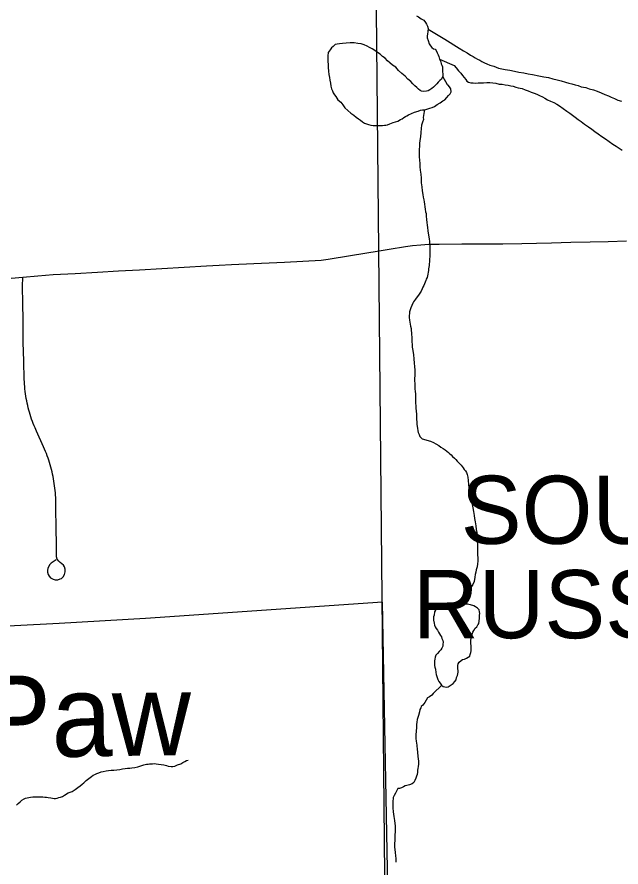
# Model space of a CAD drawing. Extents: x 103424 to 290657, y 38711 to 110967.
# Drawn here: x 117188 to 121647, y 46874 to 53149 of the extents above; entities that cross this region are included whole.
import ezdxf

# ---------------------------------------------------------------- set-up
doc = ezdxf.new("R2010")
doc.units = 0
for name, color, linetype in [('GM_X_Corporation', 7, 'Continuous'), ('GM_X_Corporation_Text', 7, 'Continuous'), ('GM_X_Minor_Lake', 7, 'Continuous'), ('GM_X_Minor_Lake_Text', 7, 'Continuous'), ('GM_X_Minor_River', 7, 'Continuous'), ('GM_X_Township_Road', 7, 'Continuous')]:
    doc.layers.add(name, color=color, linetype=linetype)

msp = doc.modelspace()

# ---------------------------------------------------------------- linework, layer by layer
at = {"layer": 'GM_X_Corporation'}
for points in [[(103423.7, 70904.9), (103423.7, 43132.7), (108691.3, 43264.4), (116952, 43470.9), (119934.2, 43543), (119908.2, 46302.1), (119859.8, 51426.6), (119800.4, 57496.9), (119747.3, 63220.6), (119711.4, 67089.1)], [(149451.3, 44180.8), (147524, 44122.7), (147511.7, 44122.4), (144100.1, 44042.4), (133604.6, 43873.3), (130307.3, 43800.5), (126993.8, 43728), (121865.1, 43580.2), (119934.2, 43543), (119908.2, 46302.1), (119859.8, 51426.6), (119800.4, 57496.9), (119747.3, 63220.6), (119711.4, 67089.1)], [(116953.7, 43492.4), (117668.8, 43508.8), (118194.1, 43520.8), (118895.2, 43536.8), (119961.9, 43561.2), (119932.5, 46334.5), (119886.4, 48829.9), (118136.2, 48708), (117498.8, 48671.3), (116838, 48636.4)]]:
    msp.add_lwpolyline(points, dxfattribs=at)
at = {"layer": 'GM_X_Minor_Lake'}
for points in [[(120331.6, 52709.7), (120327.7, 52701.6), (120321.8, 52691.4), (120309.9, 52681.1), (120298, 52668.8), (120286.1, 52656.5), (120276.2, 52646.2), (120262.3, 52631.8), (120250.3, 52621.5), (120236.4, 52611.2), (120224.4, 52604.9), (120210.3, 52600.7), (120190.2, 52598.3), (120174, 52602.1), (120163.9, 52606), (120151.6, 52615.9), (120139.3, 52627.8), (120124.9, 52641.7), (120110.6, 52655.6), (120094.1, 52673.5), (120073.6, 52691.3), (120053.1, 52711.2), (120028.5, 52733), (120003.9, 52754.8), (119983.4, 52778.8), (119958.9, 52794.5), (119940.5, 52810.4), (119924, 52826.3), (119905.6, 52844.1), (119887.2, 52858), (119868.8, 52873.8), (119850.4, 52887.7), (119830, 52901.5), (119809.6, 52913.3), (119791.2, 52925.1), (119772.9, 52934.9), (119750.5, 52944.6), (119728.2, 52950.3), (119704, 52954), (119677.7, 52957.6), (119647.4, 52959.1), (119617.1, 52956.6), (119591, 52954.1), (119568.8, 52951.8), (119550.7, 52947.4), (119536.6, 52945.2), (119522.7, 52930.8), (119510.8, 52920.5), (119501, 52906.2), (119485.1, 52887.7), (119483.6, 52861.5), (119481.9, 52841.2), (119482.2, 52821), (119484.6, 52798.9), (119485, 52776.6), (119487.5, 52748.4), (119489.9, 52724.2), (119494.3, 52702), (119496.7, 52681.9), (119501.1, 52659.7), (119505.4, 52639.6), (119509.8, 52619.5), (119516.1, 52603.4), (119522.4, 52589.4), (119530.7, 52575.4), (119541.1, 52561.4), (119555.6, 52537.4), (119578.1, 52519.6), (119592.5, 52501.7), (119609, 52479.7), (119629.6, 52457.8), (119652.1, 52440), (119674.5, 52424.2), (119692.9, 52410.4), (119709.3, 52396.5), (119723.6, 52386.6), (119737.9, 52374.7), (119754.2, 52364.9), (119782.6, 52355.3), (119800.9, 52351.5), (119817.1, 52347.8), (119833.2, 52348), (119851.4, 52348.3), (119871.5, 52348.6), (119885.7, 52348.9), (119899.8, 52351.1), (119911.8, 52351.3), (119921.9, 52353.5), (119940, 52359.9), (119964, 52370.4), (119998.1, 52381), (120018.1, 52391.5), (120032.1, 52397.7), (120044.1, 52406), (120056.1, 52414.3), (120066.1, 52418.5), (120078.1, 52426.8), (120122.1, 52445.7), (120150.2, 52454.2), (120166.3, 52460.6), (120180.4, 52462.8)], [(120180.4, 52462.8), (120194.5, 52465), (120206.5, 52467.3), (120220.6, 52471.5), (120236.7, 52475.8), (120252.7, 52480.1), (120270.8, 52488.5), (120290.7, 52503), (120312.7, 52515.5), (120330.6, 52529.9), (120346.6, 52538.2), (120360.5, 52554.7), (120374.3, 52569), (120386.2, 52581.3), (120392, 52597.6), (120389.6, 52619.8), (120381.3, 52633.8), (120371, 52645.7), (120367, 52647.7), (120331.6, 52709.7)], [(120363.7, 48821.6), (120339.5, 48813.6), (120327.5, 48809.6), (120315.4, 48799.5), (120301.3, 48789.4), (120289.2, 48781.4), (120277.1, 48769.3), (120271.1, 48757.2), (120267.1, 48733), (120263, 48720.9), (120263, 48696.8), (120267, 48672.6), (120271, 48658.5), (120275, 48646.4), (120283.1, 48634.3), (120291.1, 48622.2), (120299.1, 48608.1), (120307.2, 48596), (120313.2, 48583.9), (120321.2, 48571.8), (120325.2, 48559.7), (120331.3, 48545.6), (120333.3, 48533.5), (120331.2, 48519.4), (120331.2, 48503.3), (120325.2, 48489.2), (120317.1, 48477.1), (120305, 48465), (120293, 48448.9), (120280.9, 48436.8), (120274.8, 48422.7), (120272.8, 48408.6), (120270.8, 48396.5), (120270.8, 48360.2), (120272.8, 48348.1), (120276.8, 48334), (120280.8, 48309.8), (120282.8, 48295.7), (120290.8, 48271.5), (120294.8, 48257.4), (120302.8, 48243.3), (120310.9, 48231.2), (120322.9, 48217.1), (120335, 48207), (120347, 48203), (120359.1, 48201), (120371.2, 48203), (120385.3, 48213.1), (120407.4, 48229.2), (120419.5, 48243.3), (120429.6, 48255.4)], [(120593.2, 48665.1), (120596.8, 48672.4), (120602.9, 48708.7), (120602.9, 48732.9), (120605, 48745), (120603, 48757.1), (120598.9, 48771.2), (120586.9, 48785.3), (120572.8, 48793.4), (120560.8, 48801.4), (120536.6, 48809.5), (120524.6, 48811.5), (120512.5, 48813.5), (120500.4, 48813.5), (120488.4, 48815.5), (120476.3, 48815.5), (120464.2, 48817.6), (120436.1, 48817.6), (120411.9, 48821.6), (120363.7, 48821.6)], [(120429.6, 48255.4), (120433.6, 48273.5), (120439.6, 48287.6), (120443.7, 48311.8), (120443.7, 48323.9), (120441.7, 48336), (120441.7, 48360.1), (120443.7, 48374.2), (120451.8, 48386.3), (120465.9, 48398.4), (120477.9, 48406.5), (120492, 48408.5), (120506.1, 48416.5), (120518.2, 48422.6), (120530.3, 48430.6), (120534.3, 48442.7), (120538.3, 48456.8), (120540.4, 48468.9), (120540.4, 48485), (120540.4, 48509.2), (120538.4, 48521.3), (120538.4, 48547.5), (120544.5, 48583.8), (120552.6, 48608), (120560.6, 48620), (120570.7, 48636.2), (120582.7, 48646.2), (120590.8, 48660.3), (120593.2, 48665.1)]]:
    msp.add_lwpolyline(points, dxfattribs=at)
at = {"layer": 'GM_X_Minor_River'}
for points in [[(120136.4, 53157), (120150.7, 53149.2), (120160.9, 53143.3), (120171.1, 53135.4), (120191.4, 53125.6), (120203.8, 53107.6), (120210.1, 53095.6), (120218.4, 53081.6), (120222.7, 53063.5), (120221.1, 53043.3), (120217.4, 53023), (120215.6, 53010.8), (120215.8, 52994.7), (120222.2, 52974.6), (120230.7, 52950.5), (120241, 52936.5), (120249.3, 52924.5), (120261.6, 52914.6), (120273.7, 52910.8), (120282, 52900.8), (120290.3, 52884.8), (120296.6, 52870.8), (120300.8, 52858.7), (120307.2, 52838.6), (120315.6, 52818.5), (120319.9, 52804.5), (120324.1, 52794.4), (120328.4, 52782.4), (120328.7, 52764.2), (120331.6, 52709.7)], [(120222.3, 53058.4), (120345.1, 52984.7), (120453.2, 52919.8), (120483.8, 52900.1), (120512.3, 52884.4), (120534.8, 52868.6), (120555.1, 52856.8), (120571.4, 52847), (120587.7, 52837.2), (120604, 52829.3), (120620.3, 52821.5), (120638.6, 52811.7), (120656.9, 52803.9), (120679.3, 52794.2), (120707.6, 52786.6), (120725.9, 52778.8), (120742.2, 52771), (120766.5, 52765.3), (120792.8, 52761.7), (120825.2, 52756.2), (120859.6, 52748.7), (120892, 52743.1), (120928.4, 52737.7), (120960.8, 52730.1), (120993.2, 52724.6), (121039.8, 52715.3), (121076.2, 52707.8), (121110.6, 52702.3), (121143.1, 52692.7), (121175.5, 52685.2), (121205.9, 52677.6), (121236.3, 52668), (121260.7, 52660.3), (121285, 52654.7), (121307.3, 52649), (121329.6, 52643.3), (121353.9, 52633.6), (121386.3, 52628), (121412.7, 52618.4), (121443.1, 52610.8), (121471.5, 52601.1), (121500, 52589.5), (121528.4, 52577.8), (121554.8, 52566.2), (121575.2, 52556.4), (121599.6, 52546.7), (121624, 52534.9), (121650.3, 52527.3)], [(120307.3, 52838.5), (120415, 52789.9), (120429.4, 52774), (120447.9, 52752), (120464.4, 52734.1), (120476.7, 52718.2), (120489.1, 52702.2), (120501.5, 52688.3), (120509.8, 52674.3), (120520, 52668.4), (120538.2, 52662.6), (120554.4, 52662.9), (120572.5, 52661.1), (120592.7, 52663.5), (120610.8, 52663.8), (120631, 52664.1), (120655.2, 52664.5), (120677.4, 52664.9), (120701.7, 52663.3), (120723.9, 52659.6), (120748.2, 52653.9), (120770.4, 52652.3), (120792.7, 52648.6), (120815, 52644.9), (120833.2, 52641.2), (120851.4, 52637.4), (120869.7, 52631.7), (120887.9, 52625.9), (120916.3, 52620.3), (120938.6, 52612.6), (120961, 52602.9), (120983.3, 52595.2), (121005.6, 52587.4), (121025.9, 52579.7), (121046.3, 52569.9), (121066.6, 52560.2), (121084.9, 52550.4), (121105.3, 52538.6), (121125.7, 52528.8), (121152.1, 52517.1), (121172.5, 52505.3), (121192.8, 52493.5), (121248, 52454), (121268.4, 52438.2), (121288.8, 52424.4), (121309.3, 52408.6), (121329.7, 52392.8), (121352.2, 52377), (121376.7, 52357.2), (121407.3, 52339.5), (121431.8, 52321.7), (121454.3, 52303.9), (121478.8, 52286.1), (121505.4, 52266.4), (121531.9, 52248.6), (121558.5, 52228.8), (121587, 52211.1), (121611.5, 52195.4), (121634, 52181.6), (121656.4, 52165.8)], [(120197.3, 52465.6), (120187.4, 52406.4), (120187.6, 52392.2), (120181.9, 52371.9), (120174.2, 52349.6), (120170.6, 52325.3), (120169, 52297), (120165.6, 52264.6), (120162, 52238.3), (120160.3, 52216), (120158.7, 52191.7), (120157, 52175.6), (120157.2, 52159.4), (120157.6, 52139.2), (120158, 52117), (120158.4, 52092.8), (120160.8, 52066.5), (120161.2, 52042.3), (120163.7, 52018.1), (120168.2, 51989.9), (120170.7, 51959.6), (120171.3, 51925.3), (120175.8, 51895.1), (120178.3, 51864.8), (120182.8, 51838.6), (120187.2, 51818.5), (120191.5, 51800.4), (120193.8, 51784.3), (120196.1, 51766.1), (120198.5, 51748), (120200.8, 51729.8), (120203.1, 51711.7), (120207.4, 51697.6), (120209.7, 51679.5), (120212.1, 51655.3), (120214.6, 51631.1), (120216.9, 51612.9), (120219.2, 51594.8), (120221.6, 51570.6), (120230.7, 51510.1), (120233, 51494), (120233.3, 51475.8), (120235.6, 51457.7), (120235.8, 51447.6), (120236, 51435.5), (120236.2, 51423.3), (120234.4, 51411.2), (120234.9, 51384.9), (120233.3, 51356.6), (120233.6, 51340.5), (120231.8, 51326.3), (120230, 51314.2), (120228.2, 51302), (120226.4, 51289.9), (120224.5, 51277.7), (120222.7, 51265.6), (120220.9, 51251.4), (120217.1, 51239.2), (120215.3, 51227), (120209.5, 51214.8), (120205.6, 51204.7), (120201.8, 51192.5), (120196, 51178.2), (120190.1, 51166), (120184.3, 51153.8), (120178.4, 51141.6), (120170.6, 51125.3), (120160.8, 51109), (120151, 51094.7), (120143.1, 51082.4), (120129.2, 51066.1), (120121.3, 51055.8), (120115.5, 51045.6), (120109.6, 51035.4), (120101.8, 51019.1), (120096, 51002.9), (120090.2, 50986.6), (120086.4, 50972.4), (120084.6, 50960.3), (120082.8, 50946.1), (120083.1, 50929.9), (120085.4, 50909.8), (120092.3, 50865.5), (120096.6, 50849.4), (120098.8, 50833.2), (120101.1, 50819.1), (120101.4, 50803), (120101.6, 50788.8), (120101.8, 50778.8), (120102, 50764.6), (120102.3, 50750.5), (120104.6, 50732.3), (120104.9, 50712.1), (120109.4, 50685.9), (120114, 50655.7), (120116.5, 50625.5), (120121, 50593.2), (120123.5, 50569), (120123.9, 50542.8), (120124.4, 50516.5), (120124.7, 50498.3)], [(120124.7, 50498.3), (120122.9, 50484.2), (120123.2, 50464), (120123.6, 50443.8), (120123.9, 50423.6), (120124.3, 50403.4), (120126.6, 50385.2), (120128.9, 50367.1), (120129.3, 50342.9), (120129.8, 50316.6), (120130.1, 50296.4), (120132.4, 50280.3), (120132.7, 50262.1), (120135.1, 50239.9), (120137.5, 50215.7), (120137.8, 50195.5), (120138.1, 50177.4), (120138.5, 50159.2), (120140.7, 50143.1), (120141, 50126.9), (120143.3, 50112.8), (120147.7, 50092.7), (120149.8, 50082.6), (120156.2, 50066.5), (120162.5, 50052.5), (120178.9, 50034.6), (120241.7, 50017.5), (120262.1, 50007.7), (120280.4, 49997.9), (120300.8, 49986.1), (120317.2, 49972.2), (120333.5, 49962.4), (120347.8, 49952.5), (120360, 49942.6), (120372.3, 49934.7), (120382.5, 49924.8), (120392.8, 49916.9), (120403.1, 49905), (120417.4, 49893.1), (120427.6, 49883.1), (120438, 49869.2), (120452.3, 49855.3), (120466.7, 49839.3), (120481.1, 49821.4), (120489.4, 49809.4), (120497.7, 49797.4), (120506, 49785.4), (120512.3, 49771.4), (120516.6, 49751.3), (120519, 49727.1), (120521.5, 49698.8), (120524, 49672.6), (120528.4, 49648.4), (120532.9, 49622.2), (120537.4, 49594), (120543.9, 49571.9), (120548.3, 49549.8), (120552.7, 49525.6), (120557.2, 49499.4), (120561.7, 49469.2), (120566.1, 49447), (120570.6, 49420.9), (120575.1, 49392.7), (120577.6, 49366.4), (120582, 49342.3), (120584.4, 49322.1), (120584.7, 49301.9), (120585.1, 49279.7), (120587.6, 49251.5), (120587.9, 49233.3), (120588.2, 49215.1), (120588.6, 49192.9), (120589.4, 49142.4), (120589.6, 49132.3), (120587.9, 49112.1), (120584.3, 49089.8), (120578.6, 49067.5), (120574.9, 49049.2), (120571.1, 49033), (120567.4, 49012.8), (120561.9, 48980.3), (120552.1, 48960), (120544.3, 48945.7), (120538.6, 48927.4), (120532.8, 48911.2), (120529, 48895), (120523.2, 48880.7), (120519.4, 48866.5), (120504.6, 48813.5)], [(120324.4, 48215.9), (120261, 48155.3), (120251.1, 48143), (120233.2, 48130.6), (120219.2, 48122.2), (120199.6, 48087.6), (120183.8, 48069.1), (120171.8, 48058.8), (120168, 48048.7), (120162.1, 48036.5), (120158.4, 48018.2), (120150.8, 47991.8), (120143.2, 47963.4), (120139.5, 47943.2), (120137.8, 47925), (120136.1, 47902.7), (120134.5, 47876.4), (120133, 47850.1), (120133.4, 47821.9), (120135.8, 47803.7), (120140.3, 47773.5), (120140.5, 47763.4), (120142.7, 47749.3), (120145.3, 47717), (120150.1, 47668.6), (120152.3, 47658.5), (120152.5, 47646.4), (120150.8, 47632.3), (120149, 47616.1), (120147.3, 47599.9), (120145.5, 47587.7), (120143.7, 47573.5), (120142, 47555.4), (120138.1, 47543.2), (120132.3, 47528.9), (120124.5, 47512.6), (120116.7, 47498.4), (120104.8, 47488.1), (120084.7, 47479.7), (120064.6, 47475.3), (120054.6, 47473.1), (120040.6, 47464.8), (120026.6, 47458.5), (120012.5, 47454.2), (120000.4, 47452), (119992.6, 47437.7), (119982.8, 47419.4), (119973, 47401.1), (119965.2, 47386.8), (119961.8, 47352.4), (119962.5, 47310), (119965, 47281.7), (119969.6, 47245.5), (119974.1, 47217.3), (119976.5, 47195.1), (119978.8, 47176.9), (119979.2, 47156.7), (119979.6, 47132.5), (119977.9, 47112.3), (119978.3, 47092.1), (119976.7, 47065.8), (119974.9, 47049.6), (119975.2, 47035.5), (119975.4, 47021.3), (119980.1, 46981), (119982.5, 46956.8), (119984.9, 46936.6), (119985.1, 46926.5), (119985.3, 46910.4), (119985.4, 46908.4)], [(117183.5, 47331), (117197.4, 47343.3), (117211.3, 47355.7), (117223.2, 47368), (117241.2, 47376.4), (117251.2, 47380.6), (117287.4, 47389.2), (117305.5, 47391.6), (117323.7, 47391.9), (117339.8, 47392.1), (117351.9, 47392.3), (117366.1, 47390.5), (117378.2, 47390.7), (117392.3, 47389), (117404.5, 47389.2), (117418.6, 47387.4), (117436.8, 47383.6), (117461.1, 47380), (117473.2, 47380.2), (117483.3, 47382.4), (117497.3, 47386.6), (117509.4, 47388.9), (117523.4, 47393.1), (117539.4, 47403.5), (117565.4, 47420.1), (117595.5, 47430.7), (117617.4, 47445.2), (117637.3, 47459.7), (117653.3, 47472), (117669.2, 47484.4), (117681.1, 47494.7), (117699, 47511.2), (117709, 47519.4), (117726.9, 47533.8), (117738.9, 47542.1), (117750.8, 47550.4), (117762.8, 47556.7), (117776.8, 47565), (117790.9, 47569.2), (117808.9, 47575.6), (117825, 47579.9), (117845.1, 47584.3), (117863.2, 47586.6), (117883.4, 47588.9), (117903.5, 47589.3), (117923.7, 47591.6), (117947.9, 47594), (117965.9, 47598.4), (117986.1, 47600.7), (118004.2, 47603), (118020.3, 47603.3), (118036.4, 47605.6), (118058.6, 47608), (118078.7, 47612.3), (118124.9, 47627.3), (118143, 47631.6), (118155, 47633.8), (118167.1, 47636), (118177.2, 47636.2), (118189.3, 47636.4), (118201.4, 47636.6), (118215.6, 47634.8), (118231.7, 47633), (118251.9, 47631.4), (118272.2, 47627.6), (118290.4, 47623.9), (118304.6, 47618.1), (118324.8, 47616.4), (118338.9, 47616.6), (118353, 47618.9), (118373.1, 47627.3), (118397.1, 47635.8), (118413.1, 47644.1), (118427.1, 47652.4), (118439.1, 47658.7), (118451.2, 47662.9)]]:
    msp.add_lwpolyline(points, dxfattribs=at)
at = {"layer": 'GM_X_Township_Road'}
msp.add_line((119860.3, 51422.8), (119875.3, 51425.2), dxfattribs=at)
for points in [[(119875.3, 51425.2), (119935.4, 51434.8), (120055, 51454.1), (120107, 51461.4), (120169.9, 51467.9), (120228.9, 51471.2), (120305.5, 51472.5), (120470.6, 51473.5), (120635.6, 51474.6), (120721.7, 51475.1)], [(120721.7, 51475.1), (120775.4, 51475.5), (120915.2, 51476.3), (121023.9, 51479), (121132.7, 51481.6), (121275.5, 51485.9), (121418.3, 51490.3), (121552.6, 51492.9), (121687, 51495.6)], [(117144, 51221), (117230.4, 51227.2), (117342.1, 51237.1), (117453.7, 51247.1), (117618.5, 51256.3), (117783.3, 51265.5), (117938, 51274.2), (118092.6, 51282.8), (118257.4, 51292.4), (118422.2, 51301.9), (118587, 51311.5), (118679.3, 51316.8), (118771.5, 51322.2), (118936.4, 51329.2), (119049.6, 51334), (119162.7, 51338.8), (119297.9, 51346.9), (119433.2, 51354.9), (119486.2, 51360.4), (119649, 51387.5), (119754.5, 51405.1), (119860.3, 51422.8)], [(117477.7, 49142), (117440.4, 49116), (117431.1, 49107.2), (117420.2, 49090.7), (117414.5, 49077.7), (117413.4, 49066.3), (117414, 49049.7), (117418.8, 49032.6), (117424.8, 49021.2), (117435.2, 49009.3), (117454.9, 48998.9), (117469.9, 48994.3), (117489.6, 48994.8), (117507.2, 49000.5), (117517, 49004.7), (117529.5, 49015.5), (117538.9, 49034.2), (117543.2, 49052.2), (117544, 49072), (117539.3, 49089.6), (117531.8, 49101.4), (117507.7, 49122.2), (117495.7, 49132.5), (117483.4, 49146.1), (117479.3, 49163.6), (117478.4, 49233.2), (117476.2, 49398.2), (117474.7, 49499.5), (117473.4, 49600.8), (117472.6, 49618.4), (117471.4, 49635.9), (117469.9, 49653.4), (117468.1, 49670.9), (117465.9, 49688.3), (117463.4, 49705.8), (117460.8, 49723.1), (117457.8, 49740.5), (117454.3, 49757.7), (117450.8, 49774.9), (117446.8, 49792), (117442.5, 49809.1), (117438, 49826), (117433.2, 49843), (117428.2, 49859.8), (117422.6, 49876.4), (117417.1, 49893.1), (117411.1, 49909.6), (117404.8, 49926.1), (117398.3, 49942.4), (117391.5, 49958.5), (117384.2, 49974.6), (117331.1, 50091.8), (117320.8, 50114.8), (117314.3, 50131), (117307.7, 50147.3), (117301.7, 50163.8), (117295.7, 50180.4), (117290.1, 50197), (117284.9, 50213.8), (117279.8, 50230.6), (117275.3, 50247.5), (117270.8, 50264.6), (117266.8, 50281.7), (117263, 50298.8), (117259.5, 50316), (117256.2, 50333.3), (117253.2, 50350.6), (117250.7, 50368.1), (117248.4, 50385.4), (117246.4, 50402.9), (117244.7, 50420.4), (117243.4, 50437.9), (117242.4, 50455.7), (117241.4, 50473), (117237.8, 50609.8), (117234.1, 50746.5), (117232.3, 50911.5), (117230.8, 51035.8), (117229.4, 51160), (117230.4, 51227.2)]]:
    msp.add_lwpolyline(points, dxfattribs=at)

# ---------------------------------------------------------------- texts
at = {"layer": 'GM_X_Corporation_Text'}
for s, p in [('SOUTH', (120463.9, 49259.3)), ('RUSSELL', (120109.7, 48562.6))]:
    msp.add_text(s, height=503.12, rotation=0.00001, dxfattribs=at).set_placement(p)
at = {"layer": 'GM_X_Minor_Lake_Text'}
msp.add_text('Paw Paw', height=604.09, rotation=0.78548, dxfattribs=at).set_placement((115110.4, 47654.2))

doc.saveas('drawing.dxf')
